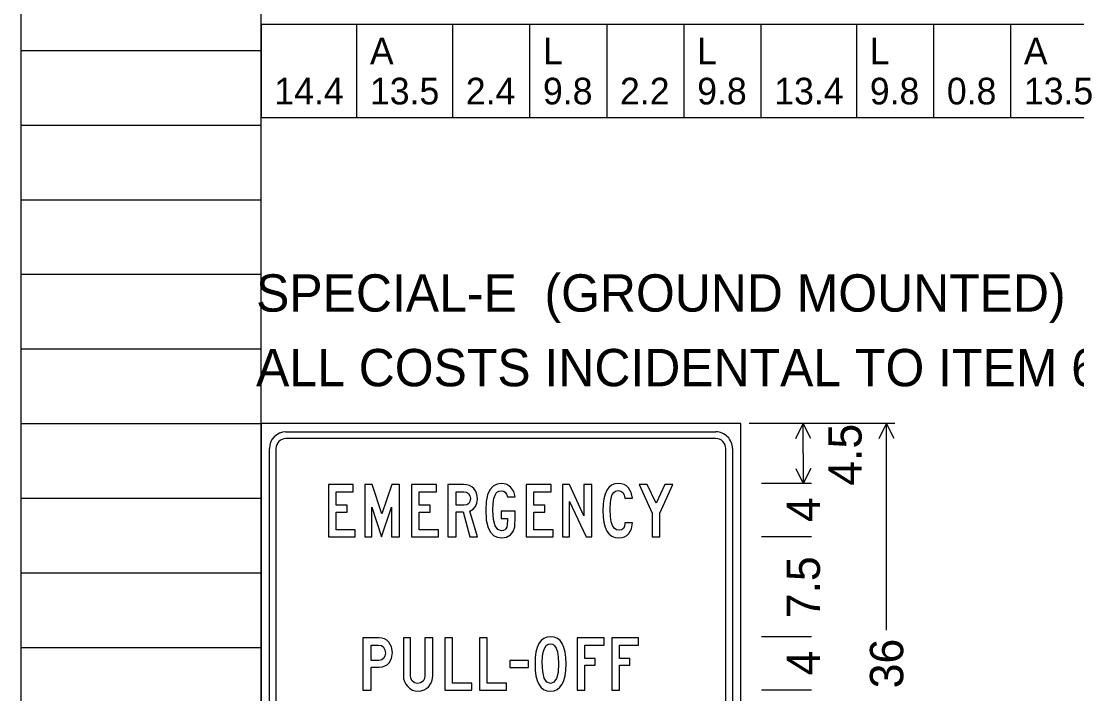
# Model space of a CAD drawing. Extents: x 1820207 to 1820557, y 740216 to 740315.
# Drawn here: x 1820476.451 to 1820480.412, y 740257.568 to 740260.092 of the extents above; entities that cross this region are included whole.
import ezdxf

# ---------------------------------------------------------------- set-up
doc = ezdxf.new("R2010")
doc.units = 0
for name, color, linetype in [('SC_Scratch1', 7, 'Continuous'), ('SC_Scratch2', 7, 'Continuous'), ('SC_Scratch3', 7, 'Continuous'), ('SH_Text', 7, 'Continuous')]:
    doc.layers.add(name, color=color, linetype=linetype)

msp = doc.modelspace()

# ---------------------------------------------------------------- linework, layer by layer
at = {"layer": 'SC_Scratch1'}
for p, q in [((1820476.451, 740255.2219), (1820476.451, 740275.3819)), ((1820477.351, 740255.2219), (1820477.351, 740275.3819)), ((1820476.451, 740259.9819), (1820477.351, 740259.9819)), ((1820476.451, 740259.7019), (1820477.351, 740259.7019)), ((1820476.451, 740259.4219), (1820477.351, 740259.4219)), ((1820476.451, 740259.1419), (1820477.351, 740259.1419)), ((1820476.451, 740258.8619), (1820477.351, 740258.8619)), ((1820476.451, 740258.5819), (1820477.351, 740258.5819)), ((1820476.451, 740258.3019), (1820477.351, 740258.3019)), ((1820476.451, 740258.0219), (1820477.351, 740258.0219)), ((1820476.451, 740257.7419), (1820477.351, 740257.7419))]:
    msp.add_line(p, q, dxfattribs=at)
at = {"layer": 'SC_Scratch2'}
msp.add_lwpolyline([(1820476.451, 740275.7419), (1820506.951, 740275.7419), (1820506.951, 740254.7419), (1820476.451, 740254.7419)], close=True, dxfattribs=at)
at = {"layer": 'SC_Scratch3'}
for p, q in [((1820477.351, 740260.0794), (1820477.351, 740259.7294)), ((1820482.7567, 740260.0794), (1820477.351, 740260.0794)), ((1820477.7096, 740260.0794), (1820477.7096, 740259.7294)), ((1820478.0693, 740260.0794), (1820478.0693, 740259.7294)), ((1820478.3588, 740260.0794), (1820478.3588, 740259.7294)), ((1820478.6478, 740260.0794), (1820478.6478, 740259.7294)), ((1820478.9374, 740260.0794), (1820478.9374, 740259.7294)), ((1820479.2264, 740260.0794), (1820479.2264, 740259.7294)), ((1820479.585, 740260.0794), (1820479.585, 740259.7294)), ((1820479.874, 740260.0794), (1820479.874, 740259.7294)), ((1820480.163, 740260.0794), (1820480.163, 740259.7294)), ((1820482.7567, 740259.7294), (1820477.351, 740259.7294)), ((1820479.7291, 740258.5819), (1820479.1822, 740258.5819)), ((1820479.4166, 740258.5819), (1820479.2291, 740258.5819)), ((1820479.3574, 740258.526), (1820479.3854, 740258.5819)), ((1820479.3854, 740258.4694), (1820479.3854, 740258.5819)), ((1820479.4133, 740258.526), (1820479.3854, 740258.5819)), ((1820479.6699, 740258.526), (1820479.6979, 740258.5819)), ((1820479.6979, 740257.8064), (1820479.6979, 740258.5819)), ((1820479.7258, 740258.526), (1820479.6979, 740258.5819)), ((1820479.3854, 740258.4694), (1820479.3854, 740258.3569)), ((1820479.3574, 740258.4128), (1820479.3854, 740258.3569)), ((1820479.4133, 740258.4128), (1820479.3854, 740258.3569)), ((1820479.4166, 740258.3569), (1820479.2291, 740258.3569)), ((1820479.4166, 740258.1569), (1820479.2291, 740258.1569)), ((1820479.4166, 740257.7819), (1820479.2291, 740257.7819)), ((1820479.4166, 740257.5819), (1820479.2291, 740257.5819))]:
    msp.add_line(p, q, dxfattribs=at)
for points in [[(1820477.351, 740256.7819), (1820479.151, 740256.7819), (1820479.151, 740258.5819), (1820477.351, 740258.5819), (1820477.351, 740256.7819), (1820477.351, 740256.7819), (1820477.351, 740256.7819)], [(1820477.4447, 740258.5507), (1820479.0572, 740258.5507)], [(1820479.0572, 740258.5257), (1820477.4447, 740258.5257)], [(1820479.0572, 740258.5257), (1820479.0572, 740258.5257), (1820479.0572, 740258.5257)], [(1820477.3822, 740256.8757), (1820477.3822, 740258.4882)], [(1820477.4072, 740258.4882), (1820477.4072, 740256.8757)], [(1820477.4072, 740258.4882), (1820477.4072, 740258.4882), (1820477.4072, 740258.4882)], [(1820479.0947, 740256.8757), (1820479.0947, 740258.4882)], [(1820479.1197, 740258.4882), (1820479.1197, 740256.8757)]]:
    msp.add_lwpolyline(points, dxfattribs=at)
for points in [[(1820478.3041, 740258.253), (1820478.2516, 740258.253), (1820478.2516, 740258.2261), (1820478.2756, 740258.2261), (1820478.2759, 740258.2193), (1820478.2751, 740258.2037), (1820478.2729, 740258.1931), (1820478.2697, 740258.1873), (1820478.2653, 740258.1832), (1820478.2598, 740258.1808), (1820478.253, 740258.18), (1820478.2389, 740258.1847), (1820478.2289, 740258.1988), (1820478.2229, 740258.2225), (1820478.2209, 740258.2556), (1820478.2218, 740258.2823), (1820478.2246, 740258.3013), (1820478.2289, 740258.3138), (1820478.235, 740258.3228), (1820478.2429, 740258.3282), (1820478.2526, 740258.33), (1820478.2609, 740258.3285), (1820478.2675, 740258.3242), (1820478.2723, 740258.317), (1820478.2755, 740258.3069), (1820478.3041, 740258.3069), (1820478.2991, 740258.3268), (1820478.2887, 740258.3425), (1820478.2812, 740258.3488), (1820478.2727, 740258.3533), (1820478.2632, 740258.356), (1820478.2526, 740258.3569), (1820478.2366, 740258.3542), (1820478.2218, 740258.3465), (1820478.2096, 740258.3335), (1820478.2009, 740258.3146), (1820478.1957, 740258.2899), (1820478.194, 740258.2595), (1820478.1962, 740258.22), (1820478.2033, 740258.1907), (1820478.2118, 740258.1741), (1820478.2232, 740258.1624), (1820478.2375, 740258.1554), (1820478.2547, 740258.1531), (1820478.2721, 740258.156), (1820478.2865, 740258.1648), (1820478.2965, 740258.1776), (1820478.3027, 740258.1947), (1820478.3047, 740258.2326)], [(1820478.7447, 740258.3021), (1820478.7399, 740258.3238), (1820478.7297, 740258.3408), (1820478.7219, 740258.3478), (1820478.7129, 740258.3529), (1820478.7026, 740258.3559), (1820478.6913, 740258.3569), (1820478.6778, 740258.3553), (1820478.6662, 740258.3505), (1820478.6562, 740258.3426), (1820478.6482, 740258.3315), (1820478.6419, 740258.3172), (1820478.6375, 740258.2998), (1820478.6348, 740258.2792), (1820478.634, 740258.2554), (1820478.6348, 740258.2314), (1820478.6376, 740258.2106), (1820478.6422, 740258.193), (1820478.6487, 740258.1787), (1820478.657, 740258.1674), (1820478.6672, 740258.1594), (1820478.6793, 740258.1546), (1820478.6933, 740258.1531), (1820478.7046, 740258.1541), (1820478.7147, 740258.1572), (1820478.7234, 740258.1624), (1820478.7309, 740258.1698), (1820478.7404, 740258.1874), (1820478.7447, 740258.2101), (1820478.716, 740258.2101), (1820478.7162, 740258.2069), (1820478.7151, 740258.1965), (1820478.711, 740258.1885), (1820478.7039, 740258.1833), (1820478.6941, 740258.1816), (1820478.6842, 740258.1835), (1820478.6761, 740258.1894), (1820478.6697, 740258.199), (1820478.6652, 740258.2127), (1820478.6624, 740258.2327), (1820478.6615, 740258.2609), (1820478.6623, 740258.2861), (1820478.6646, 740258.3035), (1820478.6686, 740258.3153), (1820478.6743, 740258.3237), (1820478.6815, 740258.3287), (1820478.6905, 740258.3304), (1820478.7004, 740258.3286), (1820478.7079, 740258.3233), (1820478.7131, 740258.3144), (1820478.716, 740258.3021)], [(1820477.7048, 740258.1838), (1820477.6326, 740258.1838), (1820477.6326, 740258.2492), (1820477.6736, 740258.2492), (1820477.6736, 740258.2761), (1820477.6326, 740258.2761), (1820477.6326, 740258.3261), (1820477.6973, 740258.3261), (1820477.6973, 740258.353), (1820477.604, 740258.353), (1820477.604, 740258.1569), (1820477.7048, 740258.1569)], [(1820477.74, 740258.1569), (1820477.7669, 740258.1569), (1820477.7669, 740258.2683), (1820477.8031, 740258.1575), (1820477.84, 740258.2683), (1820477.84, 740258.1569), (1820477.8705, 740258.1569), (1820477.8705, 740258.353), (1820477.8418, 740258.353), (1820477.8048, 740258.2439), (1820477.7678, 740258.353), (1820477.74, 740258.353)], [(1820478.0168, 740258.1838), (1820477.9446, 740258.1838), (1820477.9446, 740258.2492), (1820477.9856, 740258.2492), (1820477.9856, 740258.2761), (1820477.9446, 740258.2761), (1820477.9446, 740258.3261), (1820478.0093, 740258.3261), (1820478.0093, 740258.353), (1820477.916, 740258.353), (1820477.916, 740258.1569), (1820478.0168, 740258.1569)], [(1820478.052, 740258.1569), (1820478.0827, 740258.1569), (1820478.0827, 740258.2503), (1820478.1089, 740258.2503), (1820478.1346, 740258.1569), (1820478.1627, 740258.1569), (1820478.1342, 740258.2536), (1820478.1464, 740258.2604), (1820478.1556, 740258.2713), (1820478.1609, 740258.2838), (1820478.1627, 740258.2981), (1820478.1619, 740258.3099), (1820478.1593, 740258.3205), (1820478.1552, 740258.3297), (1820478.1494, 740258.3377), (1820478.1418, 740258.3444), (1820478.1328, 740258.3492), (1820478.1224, 740258.3521), (1820478.1106, 740258.353), (1820478.052, 740258.353)], [(1820478.0827, 740258.2761), (1820478.0827, 740258.3261), (1820478.1115, 740258.3261), (1820478.1216, 740258.3244), (1820478.1296, 740258.3193), (1820478.1348, 740258.3113), (1820478.1366, 740258.301), (1820478.135, 740258.2901), (1820478.1305, 740258.2823), (1820478.123, 740258.2776), (1820478.1125, 740258.2761)], [(1820478.4468, 740258.1838), (1820478.3746, 740258.1838), (1820478.3746, 740258.2492), (1820478.4156, 740258.2492), (1820478.4156, 740258.2761), (1820478.3746, 740258.2761), (1820478.3746, 740258.3261), (1820478.4393, 740258.3261), (1820478.4393, 740258.353), (1820478.346, 740258.353), (1820478.346, 740258.1569), (1820478.4468, 740258.1569)], [(1820478.482, 740258.1569), (1820478.5089, 740258.1569), (1820478.5089, 740258.2894), (1820478.5708, 740258.1569), (1820478.5927, 740258.1569), (1820478.5927, 740258.353), (1820478.5627, 740258.353), (1820478.5627, 740258.236), (1820478.5089, 740258.353), (1820478.482, 740258.353)], [(1820478.8659, 740258.353), (1820478.8333, 740258.2833), (1820478.8, 740258.353), (1820478.77, 740258.353), (1820478.8188, 740258.2458), (1820478.8188, 740258.1569), (1820478.8471, 740258.1569), (1820478.8471, 740258.2458), (1820478.8966, 740258.353)], [(1820477.7935, 740257.778), (1820477.733, 740257.778), (1820477.733, 740257.5819), (1820477.7637, 740257.5819), (1820477.7637, 740257.6686), (1820477.7948, 740257.6686), (1820477.8062, 740257.6695), (1820477.8161, 740257.6724), (1820477.8247, 740257.6772), (1820477.8318, 740257.6839), (1820477.8407, 740257.7009), (1820477.8437, 740257.7233), (1820477.8403, 740257.7444), (1820477.8304, 740257.7617), (1820477.8228, 740257.7688), (1820477.8141, 740257.774), (1820477.8043, 740257.777)], [(1820477.885, 740257.778), (1820477.885, 740257.636), (1820477.8861, 740257.6245), (1820477.8892, 740257.6139), (1820477.8943, 740257.6041), (1820477.9014, 740257.5951), (1820477.9098, 740257.5876), (1820477.9193, 740257.5823), (1820477.9297, 740257.5791), (1820477.9411, 740257.5781), (1820477.9522, 740257.5791), (1820477.9625, 740257.5825), (1820477.9718, 740257.5881), (1820477.9803, 740257.596), (1820477.987, 740257.605), (1820477.9918, 740257.6148), (1820477.9947, 740257.6253), (1820477.9957, 740257.6366), (1820477.9957, 740257.778), (1820477.9657, 740257.778), (1820477.9657, 740257.6378), (1820477.964, 740257.6255), (1820477.9589, 740257.6158), (1820477.9499, 740257.6088), (1820477.9382, 740257.6064), (1820477.9271, 740257.6088), (1820477.9186, 740257.6162), (1820477.9135, 740257.626), (1820477.9119, 740257.6378), (1820477.9119, 740257.778)], [(1820478.041, 740257.5819), (1820478.1418, 740257.5819), (1820478.1418, 740257.6082), (1820478.0693, 740257.6082), (1820478.0693, 740257.778), (1820478.041, 740257.778)], [(1820478.171, 740257.5819), (1820478.2718, 740257.5819), (1820478.2718, 740257.6082), (1820478.1993, 740257.6082), (1820478.1993, 740257.778), (1820478.171, 740257.778)], [(1820478.4957, 740257.6803), (1820478.4947, 740257.704), (1820478.492, 740257.7247), (1820478.4875, 740257.7421), (1820478.4812, 740257.7565), (1820478.4729, 740257.7675), (1820478.463, 740257.7755), (1820478.4512, 740257.7803), (1820478.4377, 740257.7819), (1820478.4239, 740257.7803), (1820478.4119, 740257.7755), (1820478.4018, 740257.7675), (1820478.3936, 740257.7565), (1820478.3872, 740257.7421), (1820478.3826, 740257.7247), (1820478.3798, 740257.704), (1820478.379, 740257.6803), (1820478.3798, 740257.6562), (1820478.3825, 740257.6355), (1820478.387, 740257.6179), (1820478.3933, 740257.6036), (1820478.4014, 740257.5924), (1820478.4113, 740257.5844), (1820478.423, 740257.5796), (1820478.4365, 740257.5781), (1820478.4503, 740257.5796), (1820478.4624, 740257.5844), (1820478.4725, 740257.5924), (1820478.4809, 740257.6036), (1820478.4873, 740257.6179), (1820478.4919, 740257.6355), (1820478.4947, 740257.6562)], [(1820478.537, 740257.5819), (1820478.5659, 740257.5819), (1820478.5659, 740257.6753), (1820478.6052, 740257.6753), (1820478.6052, 740257.7011), (1820478.5659, 740257.7011), (1820478.5659, 740257.7511), (1820478.6378, 740257.7511), (1820478.6378, 740257.778), (1820478.537, 740257.778)], [(1820478.667, 740257.5819), (1820478.6959, 740257.5819), (1820478.6959, 740257.6753), (1820478.7352, 740257.6753), (1820478.7352, 740257.7011), (1820478.6959, 740257.7011), (1820478.6959, 740257.7511), (1820478.7678, 740257.7511), (1820478.7678, 740257.778), (1820478.667, 740257.778)], [(1820477.7939, 740257.6934), (1820477.7637, 740257.6934), (1820477.7637, 740257.7511), (1820477.792, 740257.7511), (1820477.8031, 740257.749), (1820477.8111, 740257.7426), (1820477.8159, 740257.733), (1820477.8176, 740257.7211), (1820477.816, 740257.7104), (1820477.8113, 740257.7018), (1820477.8037, 740257.6955)], [(1820478.4674, 740257.6812), (1820478.4655, 740257.6485), (1820478.4597, 740257.6252), (1820478.4501, 740257.6112), (1820478.4368, 740257.6066), (1820478.4232, 740257.6115), (1820478.4136, 740257.6264), (1820478.4078, 740257.6512), (1820478.4059, 740257.6861), (1820478.4071, 740257.7092), (1820478.4108, 740257.7285), (1820478.4152, 740257.7403), (1820478.4211, 740257.7488), (1820478.4282, 740257.7538), (1820478.4368, 740257.7556), (1820478.4452, 740257.7537), (1820478.4524, 740257.7481), (1820478.4582, 740257.7388), (1820478.4627, 740257.7259), (1820478.4662, 740257.7055)], [(1820478.285, 740257.6665), (1820478.3542, 740257.6665), (1820478.3542, 740257.6934), (1820478.285, 740257.6934)]]:
    msp.add_lwpolyline(points, close=True, dxfattribs=at)
for centre, radius, start, end in [((1820477.4447, 740258.4882), 0.0625, 90.0002, 179.9999), ((1820477.4447, 740258.4882), 0.0375, 90.0002, 179.9998), ((1820479.0572, 740258.4882), 0.0625, 0, 90.0002), ((1820479.0572, 740258.4882), 0.0375, 0, 90.0002)]:
    msp.add_arc(centre, radius, start, end, dxfattribs=at)

# ---------------------------------------------------------------- texts
for s, p in [('A', (1820477.7596, 740259.9294)), ('L', (1820478.4088, 740259.9294)), ('L', (1820478.9874, 740259.9294)), ('L', (1820479.635, 740259.9294)), ('A', (1820480.213, 740259.9294)), ('14.4', (1820477.401, 740259.7794)), ('13.5', (1820477.7596, 740259.7794)), ('2.4', (1820478.1193, 740259.7794)), ('9.8', (1820478.4088, 740259.7794)), ('2.2', (1820478.6978, 740259.7794)), ('9.8', (1820478.9874, 740259.7794)), ('13.4', (1820479.2764, 740259.7794)), ('9.8', (1820479.635, 740259.7794)), ('0.8', (1820479.924, 740259.7794)), ('13.5', (1820480.213, 740259.7794))]:
    msp.add_text(s, height=0.1, dxfattribs=at).set_placement(p)
for s, p in [('4.5', (1820479.6041, 740258.3487)), ('4', (1820479.4479, 740258.2121)), ('7.5', (1820479.4479, 740257.8516)), ('36', (1820479.7604, 740257.5887)), ('4', (1820479.4479, 740257.6371))]:
    msp.add_text(s, height=0.125, rotation=90.0002, dxfattribs=at).set_placement(p)
at = {"layer": 'SH_Text'}
for s, p in [('SPECIAL-E  (GROUND MOUNTED)', (1820477.3324, 740259.0019)), ('ALL COSTS INCIDENTAL TO ITEM 614 - MAINTAINING TRAFFIC', (1820477.3324, 740258.7219))]:
    msp.add_text(s, height=0.14, dxfattribs=at).set_placement(p)

doc.saveas('drawing.dxf')
